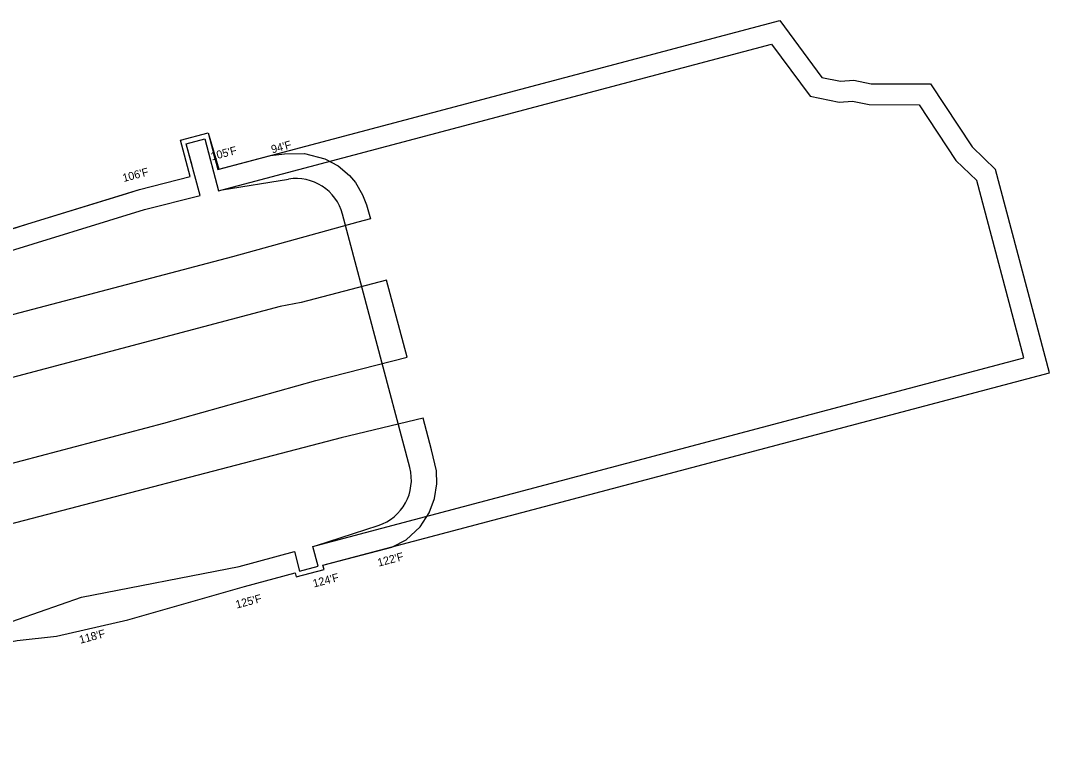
# Model space of a CAD drawing. Extents: x 2110378 to 2113376, y 867150 to 868109.
# Drawn here: x 2111021 to 2111663, y 867190 to 867648 of the extents above; entities that cross this region are included whole.
import ezdxf

# ---------------------------------------------------------------- set-up
doc = ezdxf.new("R2010")
doc.units = 0
for name, color, linetype in [('RD_PD_BCA', 7, 'Continuous'), ('RD_PD_CstnLmt', 7, 'Continuous'), ('RD_PD_DR_ErosCtrl', 7, 'Continuous'), ('RD_PD_TX_CstnLmt', 7, 'Continuous'), ('RD_Sketch1', 7, 'Continuous')]:
    doc.layers.add(name, color=color, linetype=linetype)

msp = doc.modelspace()

# ---------------------------------------------------------------- linework, layer by layer
at = {"layer": 'RD_PD_BCA'}
for p, q in [((2111146.8, 867542.08), (2111489.75, 867632.98)), ((2111647.47, 867437.09), (2111618.1, 867547.88)), ((2111205.67, 867319.99), (2111647.47, 867437.09))]:
    msp.add_line(p, q, dxfattribs=at)
for points in [[(2111489.75, 867632.98), (2111513.87, 867600.6), (2111532.05, 867596.88), (2111540.38, 867597.45), (2111550.79, 867595.3), (2111582.11, 867595.28)], [(2111582.11, 867595.28), (2111604.96, 867560.5), (2111618.1, 867547.88)]]:
    msp.add_lwpolyline(points, dxfattribs=at)
at = {"layer": 'RD_PD_CstnLmt'}
for p, q in [((2111146.8, 867542.08), (2111188.21, 867548.8)), ((2111002.71, 867500.26), (2111098.35, 867529.73)), ((2111263.95, 867368.63), (2111222.01, 867526.87)), ((2111205.67, 867319.99), (2111244.16, 867332.4)), ((2111157.43, 867306.83), (2111191.9, 867316.23)), ((2111191.9, 867316.23), (2111195.15, 867303.98)), ((2111203.48, 867319.39), (2111205.67, 867319.99)), ((2111206.75, 867307.05), (2111203.48, 867319.39)), ((2111059.04, 867287.75), (2111157.43, 867306.83)), ((2111195.15, 867303.98), (2111206.75, 867307.05)), ((2110964.32, 867254.8), (2111059.04, 867287.75))]:
    msp.add_line(p, q, dxfattribs=at)
for points in [[(2111098.35, 867529.73), (2111132.98, 867538.56), (2111124.41, 867570.87), (2111136.01, 867573.95), (2111144.61, 867541.52), (2111146.8, 867542.08)], [(2111128, 867557.34), (2111124.41, 867570.87), (2111136.01, 867573.95), (2111139.6, 867560.42)]]:
    msp.add_lwpolyline(points, dxfattribs=at)
for centre, start, end in [((2111193.01, 867519.19), 14.84478, 99.21617), ((2111234.95, 867360.95), 287.86488, 14.84478)]:
    msp.add_arc(centre, 30, start, end, dxfattribs=at)
at = {"layer": 'RD_PD_DR_ErosCtrl'}
for p, q in [((2111095.14, 867542.33), (2111126.75, 867550.35)), ((2110998.88, 867512.69), (2111095.14, 867542.33)), ((2111192.33, 867302.89), (2111193.02, 867300.31)), ((2111193.02, 867300.31), (2111210.42, 867304.92)), ((2111210.42, 867304.92), (2111209.7, 867307.61)), ((2111087.85, 867273.53), (2111160.85, 867294.29))]:
    msp.add_line(p, q, dxfattribs=at)
for points in [[(2111144.18, 867554.84), (2111494.93, 867647.8), (2111521.33, 867612.34), (2111532.92, 867609.97), (2111541.26, 867610.54), (2111552.12, 867608.3), (2111589.13, 867608.27), (2111615.02, 867568.86), (2111629.73, 867554.73)], [(2111126.75, 867550.35), (2111120.74, 867573.01), (2111138.14, 867577.62), (2111144.18, 867554.84)], [(2111209.7, 867307.61), (2111663.36, 867427.85), (2111629.73, 867554.73)], [(2111160.85, 867294.29), (2111192.33, 867302.89)], [(2110674.94, 867190.12), (2110705.68, 867196.45), (2110723.79, 867199.86), (2110746.17, 867203.57), (2110775.12, 867203.67), (2110822.94, 867219.17), (2110837.28, 867223.06), (2110863.13, 867227.2), (2110901.69, 867231.9), (2110930.34, 867240.47), (2110943.36, 867243.87), (2110978.83, 867253.13), (2111018.72, 867260.75), (2111043.46, 867263.39), (2111087.85, 867273.53)]]:
    msp.add_lwpolyline(points, dxfattribs=at)
at = {"layer": 'RD_Sketch1'}
for points in [[(2110986.86, 867508.56), (2111025.48, 867520.88), (2111087.18, 867539.88), (2111095.14, 867542.33), (2111126.75, 867550.35), (2111120.74, 867573.01), (2111138.14, 867577.62), (2111144.72, 867554.91), (2111176.91, 867563.51), (2111185.65, 867564.59), (2111198.32, 867564.88), (2111210.97, 867561.54), (2111219.17, 867557.02), (2111226.28, 867550.96), (2111229.96, 867546.59), (2111234.52, 867539.01), (2111236.98, 867532.7), (2111239.34, 867523.94), (2111231.61, 867521.85), (2111153.33, 867500.21), (2110872.46, 867426.33)], [(2111018.72, 867260.75), (2111043.46, 867263.39), (2111087.85, 867273.53), (2111160.85, 867294.29), (2111160.85, 867294.29), (2111192.33, 867302.89), (2111193.02, 867300.31), (2111210.42, 867304.92), (2111209.66, 867307.62), (2111248.8, 867317.97), (2111252.75, 867319.02), (2111261.69, 867323.52), (2111270.45, 867331.69), (2111276.06, 867340.31), (2111279.48, 867349.39), (2111280.89, 867358.59), (2111280.61, 867366.53), (2111277.59, 867379.64), (2111272.3, 867399.59), (2111221.14, 867387.23), (2110999.3, 867329.24)]]:
    msp.add_lwpolyline(points, dxfattribs=at)
msp.add_lwpolyline([(2110398.77, 867260.06), (2110410.77, 867213.13), (2110455.1, 867224.38), (2110499.31, 867234.55), (2110511.52, 867237.66), (2110722.77, 867294.01), (2110955.73, 867355.66), (2111110.41, 867396.31), (2111205.39, 867422.98), (2111262.22, 867437.62), (2111249.46, 867485.75), (2111196.19, 867471.78), (2111183.06, 867469.32), (2110919.88, 867399.53), (2110570.18, 867307.24), (2110420.71, 867266.63)], close=True, dxfattribs=at)

# ---------------------------------------------------------------- texts
at = {"layer": 'RD_PD_TX_CstnLmt'}
for s, p in [("94'F", (2111178.09, 867564.84)), ("105'F", (2111140.4, 867560.39)), ("106'F", (2111085.3, 867546.96)), ("122'F", (2111244.54, 867306.74)), ("124'F", (2111204.15, 867293.72)), ("125'F", (2111155.91, 867280.56)), ("118'F", (2111058.28, 867258.6))]:
    msp.add_text(s, height=5, rotation=14.84478, dxfattribs=at).set_placement(p)

doc.saveas('drawing.dxf')
